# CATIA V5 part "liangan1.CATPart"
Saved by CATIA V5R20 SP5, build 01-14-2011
Part number: 连杆1
Bounding box of the stored display mesh (mm): x -20 to 170, y -20 to 20, z 0 to 40
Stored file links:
  E:\scc\liangan\新建文件夹\liangan1.CATPart
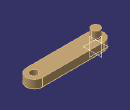
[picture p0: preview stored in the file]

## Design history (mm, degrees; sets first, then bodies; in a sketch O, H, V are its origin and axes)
Body1 (main body)
  Sketch1 on xy-plane, origin (0, 0, 0), H (1, 0, 0), V (0, 1, 0)
    construction line L1 (0, 0) -> (150, 0)
    line L2 (0, 20) -> (150, 20)
    line L3 (150, -20) -> (0, -20)
    arc A1 centre (150, 0) radius 20 from (150, 20) to (150, -20) cw
    arc A2 centre (0, 0) radius 20 from (0, -20) to (0, 20) cw
    circle A3 centre (150, 0) radius 10
    distance L1 L2 = 20
    radius A3 = 10
    horizontal: L1 H
    tangency: A1 L2, A2 L2, A1 L3, A2 L3
  Pad1: profile Sketch1, direction (0, 0, 1), length 20
  Sketch2 on end face of Pad1, origin (0, 0, 20), H (1, 0, 0), V (0, 1, 0)
    circle A1 centre (0, 0) radius 10
    radius A1 = 10
  Pad2: profile Sketch2, direction (0, 0, 1), length 20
